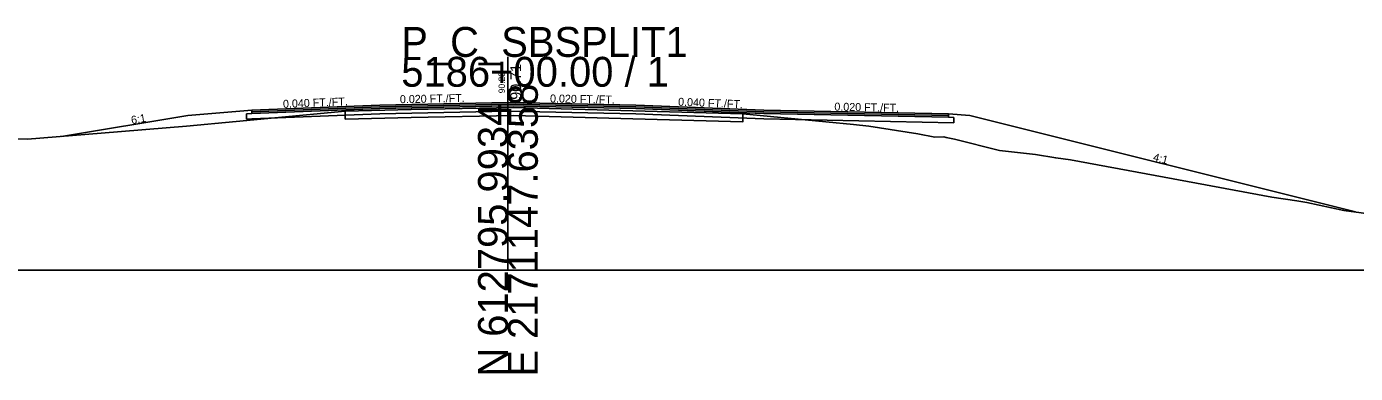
# Model space of a CAD drawing. Extents: x -26 to 1303, y -3010 to 12033.
# Drawn here: x 104.9 to 229.4, y 7490.3 to 7522.8 of the extents above; entities that cross this region are included whole.
import ezdxf

# ---------------------------------------------------------------- set-up
doc = ezdxf.new("R2010")
doc.units = 0
for name, color, linetype in [('RD_GPK_XS_Cell', 7, 'Continuous'), ('RD_XS_Base', 7, 'Continuous'), ('RD_XS_ExGround', 7, 'Continuous'), ('RD_XS_ExPaveRet', 7, 'Continuous'), ('RD_XS_Greenside', 7, 'Continuous'), ('RD_XS_Pave', 7, 'Continuous'), ('RD_XS_PaveOvlay_CP', 7, 'Continuous'), ('RD_XS_TieSlope', 7, 'Continuous'), ('RD_XS_TX_Elev_EX', 7, 'Continuous'), ('RD_XS_TX_Elev_PR', 7, 'Continuous'), ('RD_XS_TX_Slope', 7, 'Continuous')]:
    doc.layers.add(name, color=color, linetype=linetype)

msp = doc.modelspace()

# ---------------------------------------------------------------- linework, layer by layer
at = {"layer": 'RD_GPK_XS_Cell'}
for p, q in [((150, 7500), (150, 7520)), ((0, 7500), (150, 7500)), ((150, 7500), (300, 7500))]:
    msp.add_line(p, q, dxfattribs=at)
at = {"layer": 'RD_XS_Base'}
for p, q in [((150, 7514.9), (150, 7515.55)), ((150, 7515.55), (150, 7515.55)), ((150, 7515.55), (150, 7515.55)), ((150, 7515.55), (150, 7515.4)), ((126, 7514.68), (125.5, 7514.66)), ((125.5, 7514.66), (125.5, 7514.66)), ((125.5, 7514.66), (125.5, 7514.16)), ((138, 7515.16), (126, 7514.68)), ((126, 7514.68), (126, 7514.68)), ((126, 7514.18), (138, 7514.66)), ((136, 7515.08), (136, 7515.08)), ((136, 7514.58), (136, 7514.58)), ((150, 7515.4), (138, 7515.16)), ((138, 7514.66), (150, 7514.9)), ((150, 7515.4), (150, 7515.4)), ((150, 7515.4), (162, 7515.16)), ((150, 7515.4), (150, 7515.4)), ((150, 7514.9), (150, 7515.4)), ((150, 7515.4), (150, 7515.4)), ((150, 7515.4), (150, 7515.4)), ((162, 7514.66), (150, 7514.9)), ((150, 7514.9), (150, 7514.9)), ((150, 7514.9), (150, 7514.9)), ((162, 7515.16), (162, 7515.16)), ((162, 7515.16), (174, 7514.68)), ((174, 7514.18), (162, 7514.66)), ((162, 7514.66), (162, 7514.66)), ((174, 7514.68), (174, 7514.68)), ((174, 7514.68), (191.3, 7514.33)), ((191.3, 7514.33), (191.3, 7514.33)), ((191.3, 7514.33), (191.8, 7514.32)), ((191.8, 7514.32), (191.8, 7514.32)), ((191.8, 7514.32), (191.8, 7513.82)), ((125.5, 7514.16), (126, 7514.18)), ((126, 7514.18), (126, 7514.18)), ((191.8, 7513.82), (174, 7514.18)), ((174, 7514.18), (174, 7514.18))]:
    msp.add_line(p, q, dxfattribs=at)
at = {"layer": 'RD_XS_ExGround'}
msp.add_lwpolyline([(99.22, 7512.48), (104.96, 7512.27), (111.88, 7512.85), (119.87, 7513.5), (124.54, 7513.93), (134.75, 7514.92), (140.92, 7515.05), (150.52, 7515.24), (161.72, 7514.93), (172.03, 7514.67), (182.38, 7513.65), (183.82, 7513.5), (188.41, 7512.77), (190.02, 7512.48), (190.86, 7512.49), (191.08, 7512.45), (191.85, 7512.28), (196.06, 7511.22), (199.44, 7510.85), (201.34, 7510.52), (202.72, 7510.35), (210.67, 7508.86), (214.55, 7508.15), (221.61, 7506.83), (223.93, 7506.5), (224.87, 7506.35), (228.36, 7505.6), (234.39, 7504.79)], dxfattribs=at)
at = {"layer": 'RD_XS_ExPaveRet'}
for points in [[(161.72, 7514.93), (150.52, 7515.24), (150.52, 7515.24), (150.52, 7515.24), (140.92, 7515.05), (140.92, 7515.05), (134.75, 7514.92), (134.75, 7514.17), (134.75, 7514.17), (140.92, 7514.3), (140.92, 7514.3), (150.52, 7514.49), (150.52, 7514.49), (150.52, 7514.49), (161.72, 7514.18), (161.72, 7514.18), (172.03, 7513.92), (172.03, 7514.67), (172.03, 7514.67), (161.72, 7514.93), (161.72, 7514.93)], [(161.72, 7514.93), (150.52, 7515.24), (140.92, 7515.05), (134.75, 7514.92), (134.75, 7514.17), (140.92, 7514.3), (150.52, 7514.49), (161.72, 7514.18), (172.03, 7513.92), (172.03, 7514.67), (161.72, 7514.93)]]:
    msp.add_lwpolyline(points, dxfattribs=at)
at = {"layer": 'RD_XS_Greenside'}
for p, q in [((120, 7514.51), (108.17, 7512.54)), ((193.3, 7514.49), (229.43, 7505.45))]:
    msp.add_line(p, q, dxfattribs=at)
at = {"layer": 'RD_XS_Pave'}
for p, q in [((138, 7515.47), (126, 7514.99)), ((150, 7515.71), (138, 7515.47)), ((150, 7515.55), (138, 7515.31)), ((138, 7515.31), (150, 7515.55)), ((162, 7515.47), (150, 7515.71)), ((150, 7515.71), (150, 7515.71)), ((150, 7515.71), (150, 7515.71)), ((150, 7515.4), (150, 7515.55)), ((150, 7515.55), (150, 7515.55)), ((150, 7515.55), (150, 7515.55)), ((150, 7515.55), (150, 7515.55)), ((150, 7515.55), (150, 7515.55)), ((150, 7515.55), (162, 7515.31)), ((162, 7515.31), (150, 7515.55)), ((150, 7515.55), (150, 7515.55)), ((150, 7515.55), (150, 7515.55)), ((150, 7515.55), (150, 7515.55)), ((150, 7515.55), (150, 7515.4)), ((174, 7514.99), (162, 7515.47)), ((162, 7515.47), (162, 7515.47)), ((138, 7515.31), (126, 7514.83)), ((126, 7514.83), (138, 7515.31)), ((126, 7514.68), (138, 7515.16)), ((126, 7514.99), (126, 7514.99)), ((126, 7514.99), (126, 7514.83)), ((126, 7514.83), (126, 7514.83)), ((126, 7514.83), (126, 7514.68)), ((136, 7515.39), (136, 7515.39)), ((136, 7515.23), (136, 7515.23)), ((136, 7515.23), (136, 7515.23)), ((136, 7515.08), (136, 7515.08)), ((138, 7515.16), (150, 7515.4)), ((150, 7515.4), (150, 7515.4)), ((150, 7515.4), (150, 7515.4)), ((150, 7515.4), (150, 7515.4)), ((150, 7515.4), (162, 7515.16)), ((162, 7515.31), (162, 7515.31)), ((162, 7515.31), (174, 7514.83)), ((174, 7514.83), (162, 7515.31)), ((162, 7515.31), (162, 7515.31)), ((162, 7515.16), (162, 7515.16)), ((162, 7515.16), (174, 7514.68)), ((191.3, 7514.65), (174, 7514.99)), ((174, 7514.99), (174, 7514.99)), ((174, 7514.83), (174, 7514.83)), ((174, 7514.83), (191.3, 7514.49)), ((191.3, 7514.49), (174, 7514.83)), ((174, 7514.83), (174, 7514.83)), ((174, 7514.68), (191.3, 7514.33)), ((174, 7514.68), (174, 7514.68)), ((191.3, 7514.49), (191.3, 7514.65)), ((191.3, 7514.65), (191.3, 7514.65)), ((191.3, 7514.33), (191.3, 7514.49)), ((191.3, 7514.49), (191.3, 7514.49))]:
    msp.add_line(p, q, dxfattribs=at)
at = {"layer": 'RD_XS_PaveOvlay_CP'}
for p, q in [((138, 7515.47), (126, 7514.99)), ((150, 7515.71), (138, 7515.47)), ((162, 7515.47), (150, 7515.71)), ((150, 7515.71), (150, 7515.71)), ((150, 7515.71), (150, 7515.71)), ((174, 7514.99), (162, 7515.47)), ((162, 7515.47), (162, 7515.47)), ((136, 7515.39), (136, 7515.39)), ((191.3, 7514.65), (174, 7514.99)), ((174, 7514.99), (174, 7514.99))]:
    msp.add_line(p, q, dxfattribs=at)
at = {"layer": 'RD_XS_TieSlope'}
for p, q in [((126, 7514.99), (120, 7514.51)), ((191.3, 7514.65), (193.3, 7514.49))]:
    msp.add_line(p, q, dxfattribs=at)

# ---------------------------------------------------------------- texts
at = {"layer": 'RD_GPK_XS_Cell'}
for s, p in [('P_C_SBSPLIT1', (140, 7520)), ('5186+00.00 / 1', (140, 7517.2))]:
    msp.add_text(s, height=2.8, dxfattribs=at).set_placement(p)
for s, p in [('E 2171147.6358', (152.8, 7490)), ('N 612795.9934', (150, 7490))]:
    msp.add_text(s, height=2.8, rotation=90, dxfattribs=at).set_placement(p)
at = {"layer": 'RD_XS_TX_Elev_EX'}
msp.add_text('90.23', height=0.6, rotation=90, dxfattribs=at).set_placement((149.72, 7516.58))
at = {"layer": 'RD_XS_TX_Elev_PR'}
msp.add_text('90.71', height=1, rotation=90, dxfattribs=at).set_placement((151.23, 7515.98))
at = {"layer": 'RD_XS_TX_Slope'}
for s, rotation, p in [('0.040 FT./FT.', 2.2906, (128.93, 7515.21)), ('0.020 FT./FT.', 1.1458, (139.88, 7515.65)), ('0.020 FT./FT.', 358.8542, (153.94, 7515.73)), ('0.040 FT./FT.', 357.7094, (165.94, 7515.42)), ('0.020 FT./FT.', 358.8542, (180.59, 7514.96)), ('6:1', 9.4623, (114.74, 7513.69)), ('4:1', 345.9638, (210.42, 7510.27))]:
    msp.add_text(s, height=0.75, rotation=rotation, dxfattribs=at).set_placement(p)

doc.saveas('drawing.dxf')
